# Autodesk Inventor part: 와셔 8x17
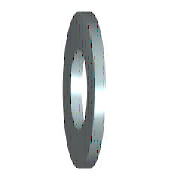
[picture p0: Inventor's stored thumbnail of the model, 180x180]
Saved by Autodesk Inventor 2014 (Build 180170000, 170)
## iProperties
IsCustomPart: 1
Created: 2012-02
Part Number: 와셔 8x17
Material: 강철, 연강
Description: 평면 와셔
Document SubType Name: Modeling
Standard: KS B 1326
Designer: mduedu
Standards Organization: KS
Language: ko-KR
Size Designation: 8x17
Categories: <MemberInstance><Categories><Category DisplayName="조임쇠" InternalName="e4da775c-781d-43d5-af7c-5136215cf5a6" Mnemonic="FSTN"><Category DisplayName="와셔" InternalN
Density: 7.86 g/cm^3
Mass: 2.15757 g
Surface Area: 4.70799 cm^2
Volume: 0.2745 cm^3
Appearance: 주황색
Author: mduedu
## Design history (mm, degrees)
sketch "스케치"
  geometry: C1 r 8.5 at (0, 0); C2 r 4.2 at (0, 0); 1 further point
  constraints: 2 centre point, 2 coincident
  dimensions: "d0" = 8.4 diameter of C2 (= SD1); "d1" = 17 diameter of C1 (= SD2)
extrude "본체" new body sketch "스케치" distance "d2" = 1.6 (= SD); taper "d3" = 0 deg
workaxis "Work Axis1"
workplane "Work Plane1"
body "Solid1"
other parameters: "SD1" = 8.4 [user parameter; used in 1 equation term], "SD2" = 17 [user parameter; used in 1 equation term], "SD" = 1.6 [user parameter; used in 1 equation term], "d4" = 0, "d5" = 0, "d6" = 0, "d7" = 0, "NND" = 8 [user parameter]
